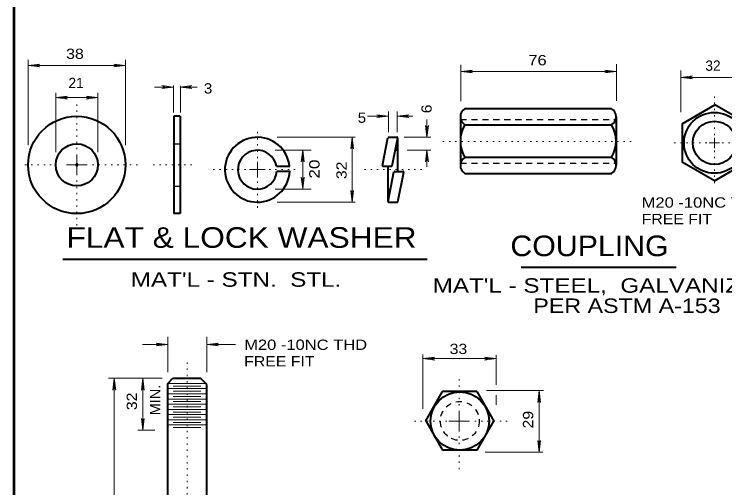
# Model space of a CAD drawing. Extents: x 312583 to 312854, y 144419 to 144597.
# Drawn here: x 312661 to 312713.4, y 144469.7 to 144504.7 of the extents above; entities that cross this region are included whole.
import ezdxf
from ezdxf.enums import TextEntityAlignment as Align

# ---------------------------------------------------------------- set-up
doc = ezdxf.new("R2010")
doc.units = 0
doc.header["$LTSCALE"] = 0.3
doc.header["$PDMODE"] = 32
doc.header["$PDSIZE"] = 0.15
doc.linetypes.add('DOTTED', pattern=[1.5, 0.3, -1.2])
doc.linetypes.add('SHORT_DASHED', pattern=[2.7, 1.5, -1.2])
doc.layers.add('1', color=7, linetype='Continuous', lineweight=25)
doc.layers.add('2', color=7, linetype='Continuous', lineweight=13)

msp = doc.modelspace()

# ---------------------------------------------------------------- linework, layer by layer
at = {"layer": '1', "lineweight": 53}
msp.add_line((312660.9631, 144423.0846), (312660.9631, 144506.4889), dxfattribs=at)
at = {"layer": '1', "lineweight": 40}
for p, q in [((312705.0711, 144497.73), (312694.2457, 144497.73)), ((312710.2767, 144496.6106), (312712.6994, 144498.0136)), ((312715.0761, 144496.6413), (312712.6994, 144498.0136)), ((312672.7404, 144497.178), (312672.7404, 144489.9866)), ((312673.2234, 144497.178), (312672.7404, 144497.178)), ((312673.2234, 144497.178), (312673.2234, 144489.9866)), ((312693.9084, 144497.1396), (312693.9084, 144493.5516)), ((312705.4084, 144497.1396), (312705.4084, 144493.5516)), ((312694.2457, 144496.5493), (312705.0711, 144496.5493)), ((312710.2767, 144496.6106), (312710.2767, 144493.7893)), ((312688.1504, 144493.5363), (312688.5568, 144495.591)), ((312688.5951, 144495.6216), (312689.2391, 144495.6216)), ((312688.8711, 144493.521), (312689.2774, 144495.5756)), ((312689.2851, 144493.1146), (312689.2851, 144495.5756)), ((312694.2457, 144494.142), (312705.0711, 144494.142)), ((312680.3304, 144493.4826), (312681.3041, 144493.4826)), ((312688.1888, 144493.4903), (312688.8328, 144493.4903)), ((312688.5644, 144490.876), (312688.5644, 144493.4826)), ((312712.6687, 144492.4093), (312710.2767, 144493.7893)), ((312712.6687, 144492.4093), (312715.0761, 144493.8046)), ((312680.3534, 144493.1146), (312681.3118, 144493.1146)), ((312688.5721, 144490.876), (312689.0014, 144493.0686)), ((312689.0398, 144493.0993), (312689.6838, 144493.0993)), ((312689.2851, 144490.8606), (312689.7221, 144493.0533)), ((312705.0787, 144492.9306), (312694.2457, 144492.9306)), ((312688.6104, 144490.83), (312689.2468, 144490.83)), ((312673.2234, 144489.9866), (312672.7404, 144489.9866)), ((312664.5547, 144486.6133), (312691.4532, 144486.6133)), ((312698.4019, 144486.023), (312709.8338, 144486.023)), ((312672.3005, 144477.444), (312672.6838, 144477.8273)), ((312672.6838, 144477.8273), (312674.7232, 144477.8273)), ((312675.1755, 144477.375), (312674.7232, 144477.8273)), ((312672.3005, 144468.2593), (312672.3005, 144477.444)), ((312675.1755, 144468.2593), (312675.1755, 144477.375)), ((312691.3445, 144474.6916), (312692.5865, 144476.8536)), ((312695.1242, 144476.8536), (312692.5865, 144476.8536)), ((312695.1242, 144476.8536), (312696.3892, 144474.6686)), ((312691.3445, 144474.6916), (312692.5942, 144472.5296)), ((312695.1472, 144472.5296), (312696.3892, 144474.6686)), ((312695.1472, 144472.5296), (312692.5942, 144472.5296))]:
    msp.add_line(p, q, dxfattribs=at)
at = {"layer": '1', "linetype": 'SHORT_DASHED'}
for p, q in [((312693.9084, 144496.925), (312705.4084, 144496.925)), ((312673.2234, 144495.1003), (312672.7404, 144495.1003)), ((312693.9084, 144493.7126), (312705.4084, 144493.7126)), ((312712.6917, 144492.4093), (312712.6687, 144492.4246)), ((312673.2234, 144491.9876), (312672.7404, 144491.9876)), ((312691.3445, 144474.6763), (312691.3598, 144474.6993))]:
    msp.add_line(p, q, dxfattribs=at)
at = {"layer": '1', "linetype": 'DOTTED', "lineweight": 13}
for p, q in [((312692.6127, 144495.315), (312706.5277, 144495.315)), ((312673.7418, 144445.7806), (312673.7418, 144479.2763)), ((312693.8208, 144475.8186), (312693.8208, 144478.065)), ((312692.9085, 144474.6686), (312690.2098, 144474.6686)), ((312694.9708, 144474.6686), (312697.6542, 144474.6686)), ((312693.8208, 144473.5186), (312693.8208, 144470.8276))]:
    msp.add_line(p, q, dxfattribs=at)
at = {"layer": '1', "lineweight": 13}
for p, q in [((312672.3005, 144477.444), (312675.1755, 144477.444)), ((312672.3005, 144477.0606), (312675.1755, 144477.0606)), ((312672.7068, 144477.2523), (312674.7462, 144477.2523)), ((312672.3005, 144476.6773), (312675.1755, 144476.6773)), ((312672.7068, 144476.869), (312674.7462, 144476.869)), ((312672.3005, 144476.294), (312675.1755, 144476.294)), ((312672.7068, 144476.4856), (312674.7462, 144476.4856)), ((312672.7068, 144476.1023), (312674.7462, 144476.1023)), ((312672.3005, 144475.9106), (312675.1755, 144475.9106)), ((312672.3005, 144475.5273), (312675.1755, 144475.5273)), ((312672.7068, 144475.719), (312674.7462, 144475.719)), ((312672.3005, 144475.144), (312675.1755, 144475.144)), ((312672.7068, 144475.3356), (312674.7462, 144475.3356)), ((312693.8208, 144474.6686), (312693.8208, 144475.4353)), ((312672.3005, 144474.7606), (312675.1755, 144474.7606)), ((312672.7068, 144474.9523), (312674.7462, 144474.9523)), ((312672.7068, 144474.569), (312674.7462, 144474.569)), ((312693.8208, 144474.6686), (312693.0542, 144474.6686)), ((312693.8208, 144474.6686), (312694.5875, 144474.6686)), ((312693.8208, 144474.6686), (312693.8208, 144473.902)), ((312672.3005, 144474.3773), (312675.1755, 144474.3773)), ((312672.7068, 144474.1856), (312674.7462, 144474.1856))]:
    msp.add_line(p, q, dxfattribs=at)
at = {"layer": '1', "lineweight": 40}
for centre, radius in [((312665.5836, 144493.5804), 3.5938), ((312712.6687, 144495.2076), 2.2466), ((312712.6679, 144495.2059), 1.5972), ((312665.5836, 144493.5823), 1.5563), ((312693.8668, 144474.6686), 2.1562)]:
    msp.add_circle(centre, radius, dxfattribs=at)
at = {"layer": '1', "linetype": 'SHORT_DASHED'}
msp.add_circle((312693.8668, 144474.6763), 1.4375, dxfattribs=at)
at = {"layer": '1', "lineweight": 40}
for centre, radius, start, end in [((312694.5931, 144497.1377), 0.6886, 120.66973, 239.33028), ((312704.716, 144497.1377), 0.6886, 300.66972, 59.33028), ((312696.2196, 144495.3418), 2.3152, 148.67471, 211.32529), ((312703.0895, 144495.3418), 2.3152, 328.67471, 31.32529), ((312678.9159, 144493.2258), 2.3958, 6.06174, 357.24751), ((312688.5933, 144495.5833), 0.0383, 90, 170.85377), ((312689.2362, 144495.5833), 0.0383, 350.82457, 90), ((312678.9159, 144493.2258), 1.4375, 10.13686, 355.4139), ((312694.5931, 144493.5459), 0.6886, 120.66972, 239.33028), ((312704.716, 144493.5459), 0.6886, 300.66973, 59.33028), ((312688.1878, 144493.5286), 0.0383, 170.82458, 270), ((312688.8308, 144493.5286), 0.0383, 270, 350.85377), ((312689.0379, 144493.0571), 0.0383, 90, 170.83462), ((312689.039, 144493.0571), 0.0383, 90, 170.80697), ((312689.6809, 144493.0571), 0.0383, 350.83463, 90), ((312688.6056, 144490.8683), 0.0383, 170.80697, 270), ((312689.2486, 144490.8683), 0.0383, 270, 350.84074)]:
    msp.add_arc(centre, radius, start, end, dxfattribs=at)
at = {"layer": '2'}
for p, q in [((312661.9918, 144495.039), (312661.9918, 144501.3333)), ((312669.1831, 144495.039), (312669.1831, 144501.3333)), ((312661.9918, 144500.9193), (312662.8581, 144501.0266)), ((312661.9918, 144500.9193), (312669.1831, 144500.9193)), ((312661.9918, 144500.9193), (312662.8581, 144500.812)), ((312662.8581, 144501.0266), (312662.5821, 144500.9193)), ((312662.8581, 144500.812), (312662.5821, 144500.9193)), ((312668.3168, 144501.0266), (312668.5928, 144500.9193)), ((312669.1831, 144500.9193), (312668.3168, 144501.0266)), ((312668.3168, 144500.812), (312668.5928, 144500.9193)), ((312669.1831, 144500.9193), (312668.3168, 144500.812)), ((312693.9467, 144500.973), (312693.9467, 144498.282)), ((312705.4467, 144501.0113), (312705.4467, 144498.3126)), ((312693.9467, 144500.4746), (312694.8131, 144500.582)), ((312693.9467, 144500.4746), (312705.4467, 144500.4746)), ((312693.9467, 144500.4746), (312694.8131, 144500.3673)), ((312694.8131, 144500.582), (312694.5371, 144500.4746)), ((312694.8131, 144500.3673), (312694.5371, 144500.4746)), ((312704.5804, 144500.582), (312704.8564, 144500.4746)), ((312705.4467, 144500.4746), (312704.5804, 144500.582)), ((312704.5804, 144500.582), (312704.8564, 144500.4746)), ((312705.4467, 144500.4746), (312704.5804, 144500.582)), ((312704.5804, 144500.3673), (312704.8564, 144500.4746)), ((312705.4467, 144500.4746), (312704.5804, 144500.3673)), ((312704.5804, 144500.3673), (312704.8564, 144500.4746)), ((312705.4467, 144500.4746), (312704.5804, 144500.3673)), ((312710.1847, 144497.477), (312710.1847, 144500.5513)), ((312710.1847, 144500.0376), (312711.0511, 144500.145)), ((312711.0511, 144500.145), (312710.7751, 144500.0376)), ((312710.1847, 144500.0376), (312715.2371, 144500.0376)), ((312710.1847, 144500.0376), (312711.0511, 144499.9303)), ((312711.0511, 144499.9303), (312710.7751, 144500.0376)), ((312671.3221, 144499.3246), (312672.7251, 144499.3246)), ((312671.8588, 144499.432), (312672.1348, 144499.3246)), ((312672.7251, 144499.3246), (312671.8588, 144499.432)), ((312671.8588, 144499.2173), (312672.1348, 144499.3246)), ((312672.7251, 144499.3246), (312671.8588, 144499.2173)), ((312672.7251, 144497.4463), (312672.7251, 144499.455)), ((312673.2234, 144499.3246), (312674.0898, 144499.432)), ((312673.2234, 144499.3246), (312674.4808, 144499.3246)), ((312673.2234, 144499.3246), (312674.0898, 144499.2173)), ((312673.2311, 144497.4463), (312673.2311, 144499.4243)), ((312674.0898, 144499.432), (312673.8138, 144499.3246)), ((312674.0898, 144499.2173), (312673.8138, 144499.3246)), ((312664.0311, 144494.5253), (312664.0311, 144498.8953)), ((312664.0311, 144498.5503), (312664.8974, 144498.6576)), ((312664.8974, 144498.6576), (312664.6214, 144498.5503)), ((312666.2774, 144498.6576), (312666.5534, 144498.5503)), ((312667.1438, 144498.5503), (312666.2774, 144498.6576)), ((312667.1438, 144494.5253), (312667.1438, 144498.8953)), ((312664.0311, 144498.5503), (312667.1438, 144498.5503)), ((312664.0311, 144498.5503), (312664.8974, 144498.443)), ((312664.8974, 144498.443), (312664.6214, 144498.5503)), ((312666.2774, 144498.443), (312666.5534, 144498.5503)), ((312667.1438, 144498.5503), (312666.2774, 144498.443)), ((312688.5951, 144496.005), (312688.5951, 144497.523)), ((312689.2391, 144496.005), (312689.2391, 144497.523)), ((312688.5951, 144497.178), (312687.0541, 144497.178)), ((312687.7288, 144497.2853), (312688.0048, 144497.178)), ((312688.5951, 144497.178), (312687.7288, 144497.2853)), ((312687.7288, 144497.0706), (312688.0048, 144497.178)), ((312688.5951, 144497.178), (312687.7288, 144497.0706)), ((312689.2391, 144497.178), (312690.1054, 144497.2853)), ((312690.4044, 144497.178), (312689.2391, 144497.178)), ((312689.2391, 144497.178), (312690.1054, 144497.0706)), ((312690.1054, 144497.2853), (312689.8294, 144497.178)), ((312690.1054, 144497.0706), (312689.8294, 144497.178)), ((312691.3321, 144496.488), (312691.4394, 144496.212)), ((312691.4394, 144495.6216), (312691.3321, 144496.488)), ((312691.4394, 144495.6216), (312691.4394, 144496.9326)), ((312691.5468, 144496.488), (312691.4394, 144496.212)), ((312691.4394, 144495.6216), (312691.5468, 144496.488)), ((312680.3688, 144495.6216), (312686.1494, 144495.6216)), ((312685.9194, 144495.6216), (312685.8121, 144494.7553)), ((312685.9194, 144490.83), (312685.9194, 144495.6216)), ((312685.9194, 144495.6216), (312686.0268, 144494.7553)), ((312689.7528, 144495.6216), (312691.7308, 144495.6216)), ((312712.6687, 144495.2076), (312712.6687, 144495.591)), ((312685.8121, 144494.7553), (312685.9194, 144495.0313)), ((312686.0268, 144494.7553), (312685.9194, 144495.0313)), ((312712.6687, 144495.2076), (312712.2854, 144495.2076)), ((312712.6687, 144495.2076), (312712.6687, 144494.8243)), ((312712.6687, 144495.2076), (312713.0521, 144495.2076)), ((312680.2231, 144494.6633), (312682.8911, 144494.6633)), ((312682.2624, 144494.6786), (312682.1551, 144493.8123)), ((312682.2624, 144491.8036), (312682.2624, 144494.6786)), ((312682.2624, 144494.6786), (312682.3698, 144493.8123)), ((312689.9674, 144494.6633), (312691.7308, 144494.6633)), ((312691.4394, 144494.6633), (312691.3321, 144493.797)), ((312691.4394, 144493.429), (312691.4394, 144494.6633)), ((312691.4394, 144494.6633), (312691.5468, 144493.797)), ((312665.5874, 144493.5823), (312665.5874, 144494.349)), ((312682.1551, 144493.8123), (312682.2624, 144494.0883)), ((312682.3698, 144493.8123), (312682.2624, 144494.0883)), ((312691.3321, 144493.797), (312691.4394, 144494.073)), ((312691.5468, 144493.797), (312691.4394, 144494.073)), ((312665.5874, 144493.5823), (312664.8208, 144493.5823)), ((312665.5874, 144493.5823), (312665.5874, 144492.8156)), ((312665.5874, 144493.5823), (312666.3541, 144493.5823)), ((312678.9198, 144493.2296), (312678.9198, 144493.8046)), ((312678.9198, 144493.2296), (312678.3448, 144493.2296)), ((312678.9198, 144493.2296), (312679.4948, 144493.2296)), ((312678.9198, 144493.2296), (312678.9198, 144492.6546)), ((312682.1551, 144492.67), (312682.2624, 144492.394)), ((312682.2624, 144491.8036), (312682.1551, 144492.67)), ((312682.3698, 144492.67), (312682.2624, 144492.394)), ((312682.2624, 144491.8036), (312682.3698, 144492.67)), ((312680.2231, 144491.7883), (312682.8911, 144491.7883)), ((312685.8121, 144491.6963), (312685.9194, 144491.4203)), ((312685.9194, 144490.83), (312685.8121, 144491.6963)), ((312686.0268, 144491.6963), (312685.9194, 144491.4203)), ((312685.9194, 144490.83), (312686.0268, 144491.6963)), ((312680.3688, 144490.83), (312686.1494, 144490.83)), ((312672.3005, 144478.2796), (312672.3005, 144480.894)), ((312675.1755, 144478.2796), (312675.1755, 144480.894)), ((312670.4375, 144480.319), (312672.3005, 144480.319)), ((312671.4342, 144480.4263), (312671.7102, 144480.319)), ((312672.3005, 144480.319), (312671.4342, 144480.4263)), ((312671.4342, 144480.2116), (312671.7102, 144480.319)), ((312672.3005, 144480.319), (312671.4342, 144480.2116)), ((312675.1755, 144480.319), (312676.0418, 144480.4263)), ((312675.1755, 144480.319), (312677.2915, 144480.319)), ((312675.1755, 144480.319), (312676.0418, 144480.2116)), ((312676.0418, 144480.4263), (312675.7658, 144480.319)), ((312676.0418, 144480.2116), (312675.7658, 144480.319)), ((312691.1452, 144479.5906), (312691.1452, 144475.5656)), ((312691.1452, 144479.2763), (312692.0115, 144479.3836)), ((312691.1452, 144479.2763), (312696.5425, 144479.2763)), ((312691.1452, 144479.2763), (312692.0115, 144479.169)), ((312692.0115, 144479.3836), (312691.7355, 144479.2763)), ((312692.0115, 144479.169), (312691.7355, 144479.2763)), ((312695.6762, 144479.3836), (312695.9522, 144479.2763)), ((312696.5425, 144479.2763), (312695.6762, 144479.3836)), ((312695.6762, 144479.169), (312695.9522, 144479.2763)), ((312696.5425, 144479.2763), (312695.6762, 144479.169)), ((312696.5425, 144479.537), (312696.5425, 144477.3366)), ((312667.9228, 144477.8273), (312670.1155, 144477.8273)), ((312668.3522, 144477.8273), (312668.2448, 144476.961)), ((312668.3522, 144448.6173), (312668.3522, 144477.8273)), ((312668.3522, 144477.8273), (312668.4595, 144476.961)), ((312669.6325, 144477.8273), (312671.8942, 144477.8273)), ((312670.4605, 144477.8273), (312670.3532, 144476.961)), ((312670.4605, 144473.994), (312670.4605, 144477.8273)), ((312670.4605, 144477.8273), (312670.5678, 144476.961)), ((312668.2448, 144476.961), (312668.3522, 144477.237)), ((312668.4595, 144476.961), (312668.3522, 144477.237)), ((312670.3532, 144476.961), (312670.4605, 144477.237)), ((312670.5678, 144476.961), (312670.4605, 144477.237)), ((312695.8372, 144476.915), (312700.0462, 144476.915)), ((312696.5425, 144476.57), (312696.5425, 144475.8646)), ((312699.7242, 144476.915), (312699.6168, 144476.0486)), ((312699.7242, 144476.915), (312699.7242, 144472.3763)), ((312699.7242, 144476.915), (312699.8315, 144476.0486)), ((312699.6168, 144476.0486), (312699.7242, 144476.3246)), ((312699.8315, 144476.0486), (312699.7242, 144476.3246)), ((312670.3532, 144474.8603), (312670.4605, 144474.5843)), ((312670.4605, 144473.994), (312670.3532, 144474.8603)), ((312670.5678, 144474.8603), (312670.4605, 144474.5843)), ((312670.4605, 144473.994), (312670.5678, 144474.8603)), ((312670.1002, 144473.994), (312671.3422, 144473.994)), ((312699.6168, 144473.2426), (312699.7242, 144472.9666)), ((312699.7242, 144472.3763), (312699.6168, 144473.2426)), ((312699.6168, 144473.2426), (312699.7242, 144472.9666)), ((312699.7242, 144472.3763), (312699.6168, 144473.2426)), ((312699.8315, 144473.2426), (312699.7242, 144472.9666)), ((312699.7242, 144472.3763), (312699.8315, 144473.2426)), ((312699.8315, 144473.2426), (312699.7242, 144472.9666)), ((312699.7242, 144472.3763), (312699.8315, 144473.2426)), ((312695.7375, 144472.3763), (312699.9925, 144472.3763))]:
    msp.add_line(p, q, dxfattribs=at)
at = {"layer": '2', "linetype": 'DOTTED'}
for p, q in [((312712.6687, 144495.7826), (312712.6687, 144498.9336)), ((312665.5874, 144494.7323), (312665.5874, 144498.0366)), ((312678.9198, 144494.0883), (312678.9198, 144496.3423)), ((312712.0937, 144495.2076), (312709.3721, 144495.2076)), ((312713.2437, 144495.2076), (312715.9347, 144495.2076)), ((312712.6687, 144494.6326), (312712.6687, 144491.9186)), ((312663.6995, 144493.5824), (312661.4861, 144493.5824)), ((312666.7374, 144493.5823), (312670.1261, 144493.5823)), ((312671.2224, 144493.5823), (312674.4041, 144493.5823)), ((312678.0611, 144493.2296), (312675.3011, 144493.2296)), ((312679.7784, 144493.2296), (312681.9788, 144493.2296)), ((312691.0638, 144493.2296), (312686.8011, 144493.2296)), ((312665.5874, 144492.4323), (312665.5874, 144488.99)), ((312678.9198, 144492.3633), (312678.9198, 144490.163))]:
    msp.add_line(p, q, dxfattribs=at)
at = {"layer": '2', "lineweight": 35}
for centre, radius, start, end in [((312689.1662, 144494.5517), 0.1169, 27.59808, 133.47727), ((312688.6527, 144491.8549), 0.1203, 225.45458, 317.09149)]:
    msp.add_arc(centre, radius, start, end, dxfattribs=at)
at = {"layer": '2'}
for p in [(312665.5874, 144493.6283), (312665.5874, 144493.5363)]:
    msp.add_point(p, dxfattribs=at)

# ---------------------------------------------------------------- texts
for s, width, p in [('38 ', 1.15, (312664.799, 144501.4044)), ('76 ', 1.2, (312698.9242, 144500.9358)), ('3 ', 1.1, (312674.967, 144498.8512)), ('5 ', 1.1, (312686.3258, 144496.6883)), ('M20 -10NC THD', 1.2, (312707.2943, 144490.4246)), ('FREE FIT', 1.15, (312707.2943, 144489.2046)), ('M20 -10NC THD', 1.2, (312677.9422, 144479.9231)), ('33 ', 1.15, (312693.1157, 144479.6147)), ('FREE FIT', 1.15, (312677.9422, 144478.7031))]:
    msp.add_text(s, height=0.76, dxfattribs=dict(at, width=width)).set_placement(p)
for s, p in [('32', (312711.9933, 144500.5304)), ('21 ', (312664.9654, 144499.2483))]:
    msp.add_text(s, height=0.76, dxfattribs=at).set_placement(p)
for s, width, p in [('6 ', 1.15, (312691.7885, 144497.3917)), ('20 ', 1.25, (312683.5059, 144492.5638)), ('32 ', 1.15, (312685.5096, 144492.5288)), ('MIN.', 1.05, (312671.7552, 144475.096)), ('32 ', 1.15, (312670.024, 144475.4733)), ('29 ', 1.15, (312699.2845, 144474.1201))]:
    msp.add_text(s, height=0.76, rotation=90, dxfattribs=dict(at, width=width)).set_placement(p)
for s, height, width, p in [('FLAT & LOCK WASHER', 1.52, 1.15, (312677.7474, 144487.4603)), (' COUPLING', 1.52, 1.1, (312703.1292, 144486.8432)), ("MAT'L - STN.  STL.", 1.07, 1.25, (312677.3446, 144484.5829)), ("MAT'L - STEEL,  GALVANIZED", 1.07, 1.25, (312704.455, 144484.1423)), ('PER ASTM A-153', 1.07, 1.2, (312706.2089, 144482.6473))]:
    msp.add_text(s, height=height, dxfattribs=dict(at, width=width)).set_placement(p, align=Align.CENTER)

doc.saveas('drawing.dxf')
